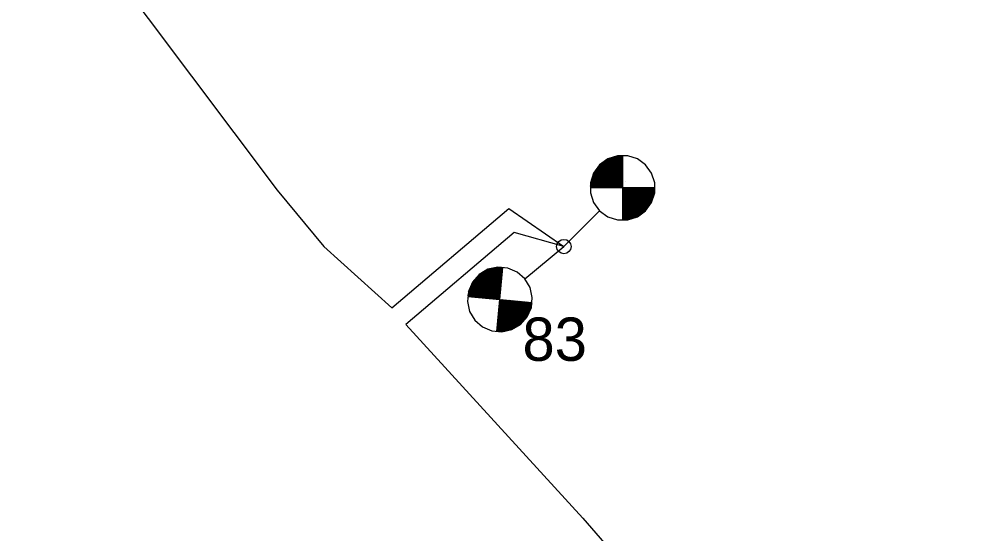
# Model space of a CAD drawing. Extents: x 25497851 to 25498523, y 6686544 to 6687372.
# Drawn here: x 25498302 to 25498368.5, y 6687273.8 to 6687309.4 of the extents above; entities that cross this region are included whole.
import ezdxf

# ---------------------------------------------------------------- set-up
doc = ezdxf.new("R2010")
doc.units = 0
for name, color, linetype in [('EL_CABLE_MAA', 7, 'Continuous'), ('KEYGWT_ANNOTATION', 7, 'Continuous'), ('Taso 1', 7, 'Continuous'), ('Taso 50', 7, 'Continuous')]:
    doc.layers.add(name, color=color, linetype=linetype)

msp = doc.modelspace()

# ---------------------------------------------------------------- linework, layer by layer
at = {"layer": 'EL_CABLE_MAA'}
for points in [[(25498310.315, 6687333.569), (25498312.763, 6687330.265), (25498301.983, 6687321.406), (25498319.845, 6687297.601), (25498323.063, 6687293.689), (25498327.772, 6687289.441), (25498335.877, 6687296.331), (25498339.678, 6687293.691)], [(25498339.678, 6687293.691), (25498336.239, 6687294.669), (25498328.744, 6687288.298), (25498340.983, 6687274.885), (25498356.843, 6687256.557), (25498365.679, 6687264.49), (25498368.532, 6687260.747)]]:
    msp.add_lwpolyline(points, dxfattribs=at)
at = {"layer": 'Taso 1'}
for p, q in [((25498343.744, 6687299.978), (25498343.744, 6687295.534)), ((25498345.965, 6687297.757), (25498341.521, 6687297.757)), ((25498342.153, 6687296.166), (25498339.678, 6687293.691)), ((25498336.981, 6687291.46), (25498339.678, 6687293.691)), ((25498335.038, 6687287.814), (25498335.456, 6687292.238)), ((25498333.036, 6687290.235), (25498337.46, 6687289.817))]:
    msp.add_line(p, q, dxfattribs=at)
for points in [[(25498345.333, 6687299.347), (25498344.764, 6687299.76), (25498344.094, 6687299.978), (25498343.391, 6687299.978), (25498342.721, 6687299.761), (25498342.152, 6687299.347), (25498341.738, 6687298.778), (25498341.521, 6687298.109), (25498341.521, 6687297.405), (25498341.739, 6687296.735), (25498342.153, 6687296.166), (25498342.722, 6687295.752), (25498343.391, 6687295.534), (25498344.095, 6687295.534), (25498344.765, 6687295.752), (25498345.334, 6687296.165), (25498345.747, 6687296.735), (25498345.965, 6687297.404), (25498345.965, 6687298.108), (25498345.747, 6687298.777)], [(25498333.515, 6687288.593), (25498334.043, 6687288.127), (25498334.689, 6687287.847), (25498335.39, 6687287.781), (25498336.076, 6687287.934), (25498336.682, 6687288.293), (25498337.147, 6687288.821), (25498337.427, 6687289.466), (25498337.493, 6687290.167), (25498337.339, 6687290.854), (25498336.981, 6687291.46), (25498336.453, 6687291.926), (25498335.807, 6687292.205), (25498335.106, 6687292.272), (25498334.419, 6687292.118), (25498333.814, 6687291.76), (25498333.348, 6687291.232), (25498333.069, 6687290.586), (25498333.003, 6687289.885), (25498333.156, 6687289.199)]]:
    msp.add_lwpolyline(points, close=True, dxfattribs=at)
msp.add_circle((25498339.678, 6687293.691), 0.5, dxfattribs=at)
at = {"layer": 'Taso 50'}
for p, q in [((25498342.188, 6687299.383), (25498343.744, 6687297.828)), ((25498342.259, 6687299.383), (25498343.744, 6687297.898)), ((25498342.294, 6687299.419), (25498343.744, 6687297.969)), ((25498342.329, 6687299.454), (25498343.744, 6687298.04)), ((25498342.365, 6687299.489), (25498343.708, 6687298.146)), ((25498343.744, 6687298.181), (25498342.4, 6687299.525)), ((25498342.437, 6687299.554), (25498343.741, 6687298.249)), ((25498343.744, 6687298.323), (25498342.506, 6687299.56)), ((25498342.541, 6687299.595), (25498343.744, 6687298.393)), ((25498342.577, 6687299.631), (25498343.744, 6687298.464)), ((25498342.612, 6687299.666), (25498343.744, 6687298.535)), ((25498342.647, 6687299.701), (25498343.744, 6687298.605)), ((25498343.744, 6687298.676), (25498342.683, 6687299.737)), ((25498343.744, 6687298.747), (25498342.754, 6687299.737)), ((25498343.744, 6687298.817), (25498342.789, 6687299.772)), ((25498343.744, 6687298.888), (25498342.86, 6687299.772)), ((25498343.744, 6687298.959), (25498342.895, 6687299.807)), ((25498343.744, 6687299.03), (25498342.966, 6687299.807)), ((25498343.744, 6687299.1), (25498343.001, 6687299.843)), ((25498343.744, 6687299.171), (25498343.072, 6687299.843)), ((25498343.744, 6687299.242), (25498343.107, 6687299.878)), ((25498343.744, 6687299.312), (25498343.178, 6687299.878)), ((25498343.744, 6687299.383), (25498343.213, 6687299.913)), ((25498343.744, 6687299.454), (25498343.284, 6687299.913)), ((25498343.744, 6687299.525), (25498343.319, 6687299.949)), ((25498343.744, 6687299.595), (25498343.39, 6687299.949)), ((25498343.744, 6687299.666), (25498343.461, 6687299.949)), ((25498343.744, 6687299.737), (25498343.496, 6687299.984)), ((25498343.744, 6687299.807), (25498343.567, 6687299.984)), ((25498343.744, 6687299.878), (25498343.673, 6687299.949)), ((25498342.683, 6687297.757), (25498341.728, 6687298.711)), ((25498342.754, 6687297.757), (25498341.764, 6687298.747)), ((25498342.824, 6687297.757), (25498341.799, 6687298.782)), ((25498342.966, 6687297.757), (25498341.834, 6687298.888)), ((25498342.895, 6687297.757), (25498341.834, 6687298.817)), ((25498343.036, 6687297.757), (25498341.87, 6687298.924)), ((25498343.107, 6687297.757), (25498341.905, 6687298.959)), ((25498343.178, 6687297.757), (25498341.94, 6687298.994)), ((25498343.249, 6687297.757), (25498341.945, 6687299.063)), ((25498343.319, 6687297.757), (25498341.976, 6687299.1)), ((25498343.39, 6687297.757), (25498342.011, 6687299.136)), ((25498343.461, 6687297.757), (25498342.046, 6687299.171)), ((25498343.531, 6687297.757), (25498342.082, 6687299.206)), ((25498342.117, 6687299.312), (25498343.673, 6687297.757)), ((25498343.602, 6687297.757), (25498342.117, 6687299.242)), ((25498342.152, 6687299.347), (25498343.744, 6687297.756)), ((25498341.976, 6687297.757), (25498341.551, 6687298.181)), ((25498341.905, 6687297.757), (25498341.551, 6687298.11)), ((25498341.834, 6687297.757), (25498341.551, 6687298.04)), ((25498342.117, 6687297.757), (25498341.587, 6687298.287)), ((25498342.046, 6687297.757), (25498341.587, 6687298.216)), ((25498342.259, 6687297.757), (25498341.622, 6687298.393)), ((25498342.188, 6687297.757), (25498341.622, 6687298.323)), ((25498342.4, 6687297.757), (25498341.658, 6687298.499)), ((25498342.329, 6687297.757), (25498341.658, 6687298.429)), ((25498342.541, 6687297.757), (25498341.693, 6687298.605)), ((25498342.471, 6687297.757), (25498341.693, 6687298.535)), ((25498342.612, 6687297.757), (25498341.728, 6687298.641)), ((25498343.92, 6687298.216), (25498343.92, 6687298.216)), ((25498341.764, 6687297.757), (25498341.516, 6687298.004)), ((25498341.693, 6687297.757), (25498341.516, 6687297.934)), ((25498341.622, 6687297.757), (25498341.516, 6687297.863)), ((25498343.743, 6687297.757), (25498345.334, 6687296.165)), ((25498343.744, 6687297.686), (25498345.299, 6687296.13)), ((25498343.744, 6687297.615), (25498345.228, 6687296.13)), ((25498343.744, 6687297.545), (25498345.193, 6687296.095)), ((25498343.744, 6687297.474), (25498345.158, 6687296.06)), ((25498343.744, 6687297.403), (25498345.122, 6687296.024)), ((25498343.814, 6687297.757), (25498345.37, 6687296.201)), ((25498343.885, 6687297.757), (25498345.37, 6687296.272)), ((25498343.956, 6687297.757), (25498345.405, 6687296.307)), ((25498344.026, 6687297.757), (25498345.441, 6687296.343)), ((25498344.097, 6687297.757), (25498345.476, 6687296.378)), ((25498344.168, 6687297.757), (25498345.511, 6687296.413)), ((25498344.238, 6687297.757), (25498345.541, 6687296.45)), ((25498344.309, 6687297.757), (25498345.547, 6687296.519)), ((25498344.38, 6687297.757), (25498345.582, 6687296.555)), ((25498344.451, 6687297.757), (25498345.617, 6687296.59)), ((25498344.521, 6687297.757), (25498345.653, 6687296.625)), ((25498344.592, 6687297.757), (25498345.688, 6687296.661)), ((25498344.663, 6687297.757), (25498345.723, 6687296.696)), ((25498344.733, 6687297.757), (25498345.747, 6687296.735)), ((25498344.804, 6687297.757), (25498345.759, 6687296.802)), ((25498344.875, 6687297.757), (25498345.759, 6687296.873)), ((25498344.946, 6687297.757), (25498345.794, 6687296.908)), ((25498345.016, 6687297.757), (25498345.794, 6687296.979)), ((25498345.087, 6687297.757), (25498345.829, 6687297.014)), ((25498345.158, 6687297.757), (25498345.829, 6687297.085)), ((25498345.228, 6687297.757), (25498345.865, 6687297.12)), ((25498345.299, 6687297.757), (25498345.865, 6687297.191)), ((25498345.37, 6687297.757), (25498345.9, 6687297.226)), ((25498345.441, 6687297.757), (25498345.9, 6687297.297)), ((25498345.511, 6687297.757), (25498345.936, 6687297.333)), ((25498345.582, 6687297.757), (25498345.972, 6687297.366)), ((25498345.653, 6687297.757), (25498345.936, 6687297.474)), ((25498345.723, 6687297.757), (25498345.936, 6687297.545)), ((25498345.794, 6687297.757), (25498345.971, 6687297.58)), ((25498345.865, 6687297.757), (25498345.971, 6687297.651)), ((25498343.744, 6687297.333), (25498345.087, 6687295.989)), ((25498343.744, 6687297.262), (25498345.049, 6687295.958)), ((25498343.744, 6687297.191), (25498344.981, 6687295.954)), ((25498343.744, 6687297.12), (25498344.946, 6687295.918)), ((25498343.744, 6687297.05), (25498344.91, 6687295.883)), ((25498343.744, 6687296.979), (25498344.875, 6687295.848)), ((25498343.744, 6687296.908), (25498344.84, 6687295.812)), ((25498343.744, 6687296.838), (25498344.804, 6687295.777)), ((25498343.744, 6687296.767), (25498344.765, 6687295.752)), ((25498343.744, 6687296.696), (25498344.698, 6687295.742)), ((25498343.744, 6687296.625), (25498344.627, 6687295.742)), ((25498343.744, 6687296.555), (25498344.592, 6687295.706)), ((25498343.744, 6687296.484), (25498344.521, 6687295.706)), ((25498343.744, 6687296.413), (25498344.486, 6687295.671)), ((25498343.744, 6687296.343), (25498344.437, 6687295.65)), ((25498343.744, 6687296.272), (25498344.38, 6687295.636)), ((25498343.744, 6687296.201), (25498344.309, 6687295.636)), ((25498343.744, 6687296.13), (25498344.274, 6687295.6)), ((25498343.744, 6687296.06), (25498344.203, 6687295.6)), ((25498343.744, 6687295.989), (25498344.168, 6687295.565)), ((25498343.744, 6687295.918), (25498344.097, 6687295.565)), ((25498343.744, 6687295.848), (25498344.062, 6687295.529)), ((25498343.744, 6687295.777), (25498343.991, 6687295.529)), ((25498343.744, 6687295.706), (25498343.92, 6687295.529)), ((25498343.744, 6687295.636), (25498343.85, 6687295.529)), ((25498335.327, 6687290.871), (25498334.339, 6687292.065)), ((25498335.334, 6687290.941), (25498334.378, 6687292.097)), ((25498335.34, 6687291.011), (25498334.419, 6687292.118)), ((25498335.347, 6687291.082), (25498334.486, 6687292.122)), ((25498335.354, 6687291.152), (25498334.557, 6687292.115)), ((25498335.36, 6687291.223), (25498334.595, 6687292.147)), ((25498335.367, 6687291.293), (25498334.666, 6687292.14)), ((25498335.374, 6687291.363), (25498334.704, 6687292.172)), ((25498335.38, 6687291.434), (25498334.756, 6687292.189)), ((25498335.387, 6687291.504), (25498334.813, 6687292.198)), ((25498335.394, 6687291.574), (25498334.884, 6687292.191)), ((25498335.4, 6687291.645), (25498334.922, 6687292.223)), ((25498335.407, 6687291.715), (25498334.993, 6687292.216)), ((25498335.414, 6687291.786), (25498335.031, 6687292.248)), ((25498335.42, 6687291.856), (25498335.101, 6687292.241)), ((25498335.427, 6687291.926), (25498335.14, 6687292.273)), ((25498335.434, 6687291.997), (25498335.21, 6687292.267)), ((25498335.44, 6687292.067), (25498335.281, 6687292.26)), ((25498335.447, 6687292.138), (25498335.351, 6687292.253)), ((25498334.614, 6687290.086), (25498333.53, 6687291.396)), ((25498334.684, 6687290.079), (25498333.569, 6687291.427)), ((25498334.754, 6687290.072), (25498333.581, 6687291.496)), ((25498334.825, 6687290.066), (25498333.614, 6687291.53)), ((25498334.895, 6687290.059), (25498333.652, 6687291.562)), ((25498334.966, 6687290.052), (25498333.691, 6687291.593)), ((25498335.036, 6687290.046), (25498333.729, 6687291.625)), ((25498335.106, 6687290.039), (25498333.768, 6687291.657)), ((25498335.177, 6687290.032), (25498333.774, 6687291.728)), ((25498335.248, 6687290.026), (25498333.814, 6687291.76)), ((25498335.254, 6687290.096), (25498333.852, 6687291.791)), ((25498335.26, 6687290.167), (25498333.922, 6687291.785)), ((25498335.267, 6687290.237), (25498333.96, 6687291.817)), ((25498335.274, 6687290.307), (25498333.999, 6687291.848)), ((25498335.28, 6687290.378), (25498334.037, 6687291.88)), ((25498335.287, 6687290.448), (25498334.076, 6687291.912)), ((25498335.294, 6687290.519), (25498334.117, 6687291.939)), ((25498335.3, 6687290.589), (25498334.185, 6687291.937)), ((25498335.307, 6687290.659), (25498334.223, 6687291.969)), ((25498335.314, 6687290.73), (25498334.262, 6687292.001)), ((25498335.32, 6687290.8), (25498334.301, 6687292.033)), ((25498333.628, 6687290.179), (25498333.15, 6687290.757)), ((25498333.698, 6687290.172), (25498333.189, 6687290.789)), ((25498333.769, 6687290.166), (25498333.195, 6687290.859)), ((25498333.839, 6687290.159), (25498333.234, 6687290.891)), ((25498333.91, 6687290.152), (25498333.24, 6687290.961)), ((25498333.98, 6687290.146), (25498333.279, 6687290.993)), ((25498334.05, 6687290.139), (25498333.286, 6687291.064)), ((25498334.121, 6687290.132), (25498333.324, 6687291.095)), ((25498334.191, 6687290.126), (25498333.331, 6687291.166)), ((25498334.262, 6687290.119), (25498333.348, 6687291.232)), ((25498334.332, 6687290.112), (25498333.376, 6687291.268)), ((25498334.402, 6687290.106), (25498333.414, 6687291.3)), ((25498334.473, 6687290.099), (25498333.453, 6687291.332)), ((25498334.543, 6687290.092), (25498333.491, 6687291.364)), ((25498333.135, 6687290.225), (25498333.04, 6687290.341)), ((25498333.206, 6687290.219), (25498333.046, 6687290.411)), ((25498333.417, 6687290.199), (25498333.065, 6687290.624)), ((25498333.276, 6687290.212), (25498333.085, 6687290.443)), ((25498333.346, 6687290.205), (25498333.092, 6687290.514)), ((25498333.487, 6687290.192), (25498333.105, 6687290.654)), ((25498333.558, 6687290.185), (25498333.143, 6687290.686)), ((25498335.028, 6687289.585), (25498335.028, 6687289.585)), ((25498336.271, 6687288.082), (25498335.187, 6687289.392)), ((25498335.194, 6687289.463), (25498336.309, 6687288.114)), ((25498336.379, 6687288.114), (25498335.203, 6687289.535)), ((25498335.207, 6687289.603), (25498336.418, 6687288.139)), ((25498336.495, 6687288.203), (25498335.221, 6687289.744)), ((25498336.534, 6687288.235), (25498335.227, 6687289.815)), ((25498336.572, 6687288.267), (25498335.234, 6687289.885)), ((25498336.643, 6687288.26), (25498335.241, 6687289.955)), ((25498336.457, 6687288.171), (25498335.246, 6687289.635)), ((25498336.682, 6687288.293), (25498335.247, 6687290.026)), ((25498336.72, 6687288.324), (25498335.318, 6687290.019)), ((25498335.388, 6687290.012), (25498336.727, 6687288.394)), ((25498335.458, 6687290.006), (25498336.765, 6687288.426)), ((25498335.529, 6687289.999), (25498336.804, 6687288.458)), ((25498335.599, 6687289.992), (25498336.842, 6687288.49)), ((25498335.67, 6687289.986), (25498336.881, 6687288.522)), ((25498335.74, 6687289.979), (25498336.915, 6687288.557)), ((25498335.81, 6687289.973), (25498336.926, 6687288.624)), ((25498335.881, 6687289.966), (25498336.964, 6687288.656)), ((25498335.951, 6687289.959), (25498337.003, 6687288.688)), ((25498336.022, 6687289.953), (25498337.041, 6687288.72)), ((25498336.092, 6687289.946), (25498337.048, 6687288.79)), ((25498336.162, 6687289.939), (25498337.087, 6687288.822)), ((25498336.233, 6687289.933), (25498337.125, 6687288.854)), ((25498336.303, 6687289.926), (25498337.164, 6687288.886)), ((25498336.374, 6687289.919), (25498337.17, 6687288.956)), ((25498336.444, 6687289.913), (25498337.209, 6687288.988)), ((25498336.514, 6687289.906), (25498337.215, 6687289.058)), ((25498336.585, 6687289.899), (25498337.254, 6687289.09)), ((25498336.655, 6687289.893), (25498337.261, 6687289.161)), ((25498336.726, 6687289.886), (25498337.299, 6687289.193)), ((25498336.796, 6687289.879), (25498337.306, 6687289.263)), ((25498336.866, 6687289.873), (25498337.344, 6687289.295)), ((25498336.937, 6687289.866), (25498337.351, 6687289.365)), ((25498337.007, 6687289.859), (25498337.39, 6687289.397)), ((25498337.078, 6687289.853), (25498337.396, 6687289.467)), ((25498337.148, 6687289.846), (25498337.403, 6687289.538)), ((25498337.218, 6687289.839), (25498337.441, 6687289.57)), ((25498337.289, 6687289.833), (25498337.448, 6687289.64)), ((25498337.359, 6687289.826), (25498337.455, 6687289.711)), ((25498335.127, 6687288.759), (25498335.829, 6687287.911)), ((25498335.134, 6687288.829), (25498335.899, 6687287.904)), ((25498335.141, 6687288.899), (25498335.937, 6687287.936)), ((25498335.147, 6687288.97), (25498336.008, 6687287.93)), ((25498335.154, 6687289.04), (25498336.046, 6687287.961)), ((25498335.161, 6687289.111), (25498336.117, 6687287.955)), ((25498336.155, 6687287.987), (25498335.167, 6687289.181)), ((25498336.194, 6687288.019), (25498335.174, 6687289.251)), ((25498336.232, 6687288.05), (25498335.181, 6687289.322)), ((25498335.061, 6687288.055), (25498335.284, 6687287.785)), ((25498335.068, 6687288.125), (25498335.322, 6687287.817)), ((25498335.074, 6687288.195), (25498335.393, 6687287.81)), ((25498335.081, 6687288.266), (25498335.463, 6687287.804)), ((25498335.087, 6687288.336), (25498335.502, 6687287.835)), ((25498335.094, 6687288.407), (25498335.572, 6687287.829)), ((25498335.101, 6687288.477), (25498335.611, 6687287.861)), ((25498335.107, 6687288.547), (25498335.681, 6687287.854)), ((25498335.114, 6687288.618), (25498335.72, 6687287.886)), ((25498335.121, 6687288.688), (25498335.79, 6687287.879)), ((25498335.048, 6687287.914), (25498335.111, 6687287.837)), ((25498335.054, 6687287.984), (25498335.214, 6687287.792))]:
    msp.add_line(p, q, dxfattribs=at)

# ---------------------------------------------------------------- texts
at = {"layer": 'KEYGWT_ANNOTATION'}
msp.add_text('83', height=3, dxfattribs=at).set_placement((25498336.812, 6687285.775))

doc.saveas('drawing.dxf')
